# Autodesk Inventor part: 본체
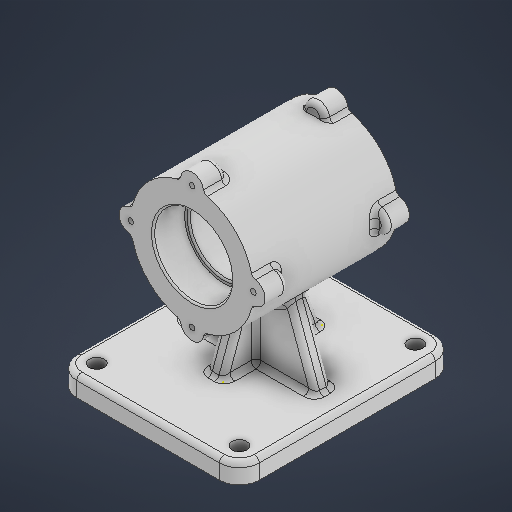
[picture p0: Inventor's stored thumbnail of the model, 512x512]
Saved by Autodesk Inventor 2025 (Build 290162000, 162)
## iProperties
Created: 2025-08
Part Number: 본체
Material: 일반
Document SubType Name: Modeling
Designer: infra012
Density: 1 g/cm^3
Appearance: 기본값
Author: infra012
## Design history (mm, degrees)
sketch "스케치1"
  geometry: 1 further point
sketch "스케치2"
  geometry: L1 (-55, -65)-(55, -65); L2 (55, -65)-(55, 65); L3 (55, 65)-(-55, 65); L4 (-55, 65)-(-55, -65); L5 (-55, -65)-(55, 65); L6 (55, -65)-(-55, 65); 1 further point
  constraints: 12 end point, 2 midpoint, 2 parallel, 1 horizontal, 1 perpendicular
  dimensions: "d0" = 110 distance of L3.end L2.end; "d1" = 130 distance of L2.end L1.end
extrude "돌출1" new body sketch "스케치2" distance "d2" = 12; taper "d3" = 0 deg
sketch "스케치3"
  geometry: 1 further point
sketch "스케치4"
  geometry: L1 (119, 38.5)-(82, 38.5); L2 (82, 38.5)-(82, -48.5); L3 (82, -48.5)-(119, -48.5); L4 (119, -48.5)-(119, 38.5); L5 (82, 38.5)-(105.5, 38.5); L6 (105.5, 38.5)-(105.5, 19.5); L7 (105.5, 19.5)-(82, 19.5); L8 (82, 19.5)-(82, 38.5); L9 (82, -48.5)-(105.5, -48.5); L10 (105.5, -48.5)-(105.5, -29.5); L11 (105.5, -29.5)-(82, -29.5); L12 (82, -29.5)-(82, -48.5); L13 (82, 19.5)-(103, 19.5); L14 (103, 19.5)-(103, -29.5); L15 (103, -29.5)-(82, -29.5); L16 (82, -29.5)-(82, 19.5); L17 (0, 65)-(12, 65) reference; L18 (0, 65)-(0, -65) reference; 6 further points
  constraints: 32 end point, 8 parallel, 4 horizontal, 4 perpendicular, 2 midpoint, 1 point on line
  dimensions: "d4" = 37 distance of L3.end L2.end; "d5" = 87 distance of L2.end L1.end; "d6" = 23.5 distance of L6.end L7.end; "d7" = 19 distance of L5.end L6.end; "d8" = 23.5 distance of L11.end L10.end; "d9" = 19 distance of L10.end L9.end; "d10" = 21 distance of L14.end L15.end; "d11" = 70 distance from line of point (82, -5) L17; "d12" = 82 distance from line of L18 point (82, -5)
revolve "회전1" sketch "스케치4" stored, may be unused: angle "d13" = 90 deg
sketch "스케치5"
  geometry: C1 r 7 at (0, 37); C2 r 7 at (-37, 0); C3 r 7 at (-37, 0); C4 r 7 at (0, -37); C5 r 7 at (37, 0); A1 r 37 centre (0, 0) between (0, 37) and (-37, 0) reference; 9 further points
  constraints: 5 centre point, 2 point on circle, 9 other
  dimensions: "d14" = 14 diameter of C1; "d15" = 14 diameter of C2; "d18" = 360 deg dimension on A1.centre C1.centre (derived)
extrude "돌출2" join sketch "스케치5" distance "d20" = 14; taper "d21" = 0 deg
sketch "스케치6"
  geometry: C1 r 7 at (0, 37); C2 r 7 at (-37, 0); C3 r 7 at (0, -37); C4 r 7 at (37, 0); 10 further points
  constraints: 4 centre point, 11 other
  dimensions: "d22" = 14 diameter of C1; "d25" = 360 deg dimension on point (0, 0) C1.centre (derived)
extrude "돌출3" join sketch "스케치6" distance "d27" = 14; taper "d28" = 0 deg
sketch "스케치7"
  geometry: 1 further point
node "스케치8"
sketch "스케치11"
  geometry: 1 further point
sketch "스케치12"
  geometry: 1 further point
sketch "스케치13"
  geometry: L1 (12, 25)-(58.061, 8.235); L2 (12, -35)-(55.537, -19.154); 3 further points
  constraints: 4 end point, 2 vertical alignment
  dimensions: "d35" = 60 distance of L2.start L1.start; "d36" = 40 distance of point (12, 65) L1.start
sketch "스케치14"
  geometry: 1 further point
sketch "스케치15"
  geometry: 1 further point
sketch "스케치16"
  geometry: 1 further point
sketch "스케치17"
  geometry: L1 (5, 35)-(-5, 35); L2 (-5, 35)-(-5, -25); L3 (-5, -25)-(5, -25); L4 (5, -25)-(5, 35); L5 (5, 35)-(-5, -25); L6 (-5, 35)-(5, -25); L7 (-55, -65)-(55, -65) reference; L8 (43, 10)-(-43, 10); L9 (-43, 10)-(-43, 0); L10 (-43, 0)-(43, 0); L11 (43, 0)-(43, 10); L12 (43, 10)-(-43, 0); L13 (-43, 10)-(43, 0); L14 (5, 0)-(-5, 0); L15 (-5, 0)-(-5, 10); L16 (-5, 10)-(5, 10); L17 (5, 10)-(5, 0); L18 (5, 0)-(-5, 10); L19 (-5, 0)-(5, 10); 6 further points
  constraints: 36 end point, 6 midpoint, 6 parallel, 3 horizontal, 3 perpendicular
  dimensions: "d39" = 10 distance of L3.end L2.end; "d40" = 60 distance of L2.end L1.end; "d41" = 70 distance from line of L7 point (0, 5); "d42" = 86 distance of L10.end L9.end; "d43" = 10 distance of L9.end L8.end; "d44" = 10 distance of L15.end L16.end; "d45" = 10 distance of L14.end L15.end
sketch "스케치18"
  geometry: 1 further point
sketch "스케치19"
  geometry: 1 further point
sketch "스케치20"
  geometry: 1 further point
extrude "돌출5" join sketch "스케치17" stored distance "d46" = 10; taper "d47" = 0 deg; dims "d4" = 37, "d5" = 87, "d6" = 23.5, "d7" = 19, "d8" = 23.5, "d9" = 19, "d10" = 21, "d11" = 70, "d12" = 82
sketch "스케치21"
  geometry: 1 further point
feature "리브1" dims "d48" = 1, "d49" = 10, "d50" = 0, "d51" = 0, "d52" = 1, "d53" = 1
sketch "스케치22"
  geometry: L1 (12, -35)-(50.309, -21.057); L2 (12, 65)-(12, -65) reference; 2 further points
  constraints: 2 end point, 1 vertical alignment
  dimensions: "d54" = 110 deg angle of L2 L1; "d55" = 60 distance of point (12, 25) L1.start
feature "리브2" sketch "스케치22" dims "d56" = 1, "d57" = 10, "d58" = 0, "d59" = 0, "d60" = 1, "d61" = 1
sketch "스케치23"
  geometry: L1 (5, 35)-(5, -25) reference; 2 further points
  constraints: 1 midpoint
sketch "스케치24"
  geometry: L1 (41, 12)-(20.479, 68.382); L2 (55, 12)-(-55, 12) reference; 1 further point
  constraints: 2 end point
  dimensions: "d62" = 14 distance of L2.start L1.start; "d63" = 60 distance of L1.start L1.end; "d64" = 110 deg angle of L2 L1; "d65" = 13.1557 distance from line of L2.start L1
feature "리브3" sketch "스케치24" dims "d66" = 1, "d67" = 10, "d68" = 0, "d69" = 0, "d70" = 1, "d71" = 1
sketch "스케치25"
  geometry: L1 (-41, 12)-(-22.486, 62.868); L2 (-55, 12)-(55, 12) reference; 1 further point
  constraints: 2 end point, 1 horizontal alignment
  dimensions: "d72" = 14 distance of L2.start L1.start; "d73" = 110 deg angle of L2 L1
feature "리브4" sketch "스케치25" dims "d74" = 1, "d75" = 10, "d76" = 0, "d77" = 0, "d78" = 1, "d79" = 1
sketch "스케치26"
  geometry: A1 r 7 centre (0, 0) between (6.969, -0.662) and (-6.969, -0.662) reference; A2 r 7 centre (-37, -37) between (-36.338, -30.031) and (-36.338, -43.969) reference; A3 r 7 centre (0, -74) between (-6.969, -73.338) and (6.969, -73.338) reference; A4 r 7 centre (37, -37) between (36.338, -43.969) and (36.338, -30.031) reference; 5 further points
  constraints: 4 coincident
hole "구멍1" sketch "스케치26" at (0, 0), (-37, -37), (0, -74), (37, -37) diameter "d80" = 3.242; stored, may be unused: countersink angle "d84" = 90 deg, drill point angle "d86" = 118 deg; dims "d81" = 8, "d82" = 4, "d83" = 2, "d85" = 10
sketch "스케치27"
  geometry: C1 r 1.621 at (0, 74) reference; C2 r 1.621 at (-37, 37) reference; C3 r 1.621 at (0, 0) reference; C4 r 1.621 at (37, 37) reference; 5 further points
  constraints: 4 coincident
hole "구멍2" sketch "스케치27" at (0, 74), (-37, 37), (0, 0), (37, 37) diameter "d87" = 3.242; stored, may be unused: countersink angle "d91" = 90 deg, drill point angle "d93" = 118 deg; dims "d88" = 8, "d89" = 4, "d90" = 2, "d92" = 10
sketch "스케치28"
  geometry: L1 (-43, -53)-(43, -53); L2 (43, -53)-(43, 53); L3 (43, 53)-(-43, 53); L4 (-43, 53)-(-43, -53); L5 (-43, -53)-(43, 53); L6 (43, -53)-(-43, 53); 5 further points
  constraints: 12 end point, 4 coincident, 2 midpoint, 2 parallel, 1 horizontal, 1 perpendicular
  dimensions: "d94" = 86 distance of L3.end L2.end; "d95" = 106 distance of L2.end L1.end
hole "구멍3" sketch "스케치28" at (43, 53), (-43, 53), (-43, -53), (43, -53) diameter "d96" = 9; stored, may be unused: countersink angle "d100" = 90 deg, drill point angle "d102" = 118 deg; dims "d97" = 8, "d98" = 4, "d99" = 2, "d101" = 10
fillet "모깎기1" dims "d103" = 12
fillet "모깎기2" dims "d104" = 3
fillet "모깎기3" dims "d105" = 3
fillet "모깎기4" dims "d106" = 3
fillet "모깎기5" dims "d107" = 1
node "솔리드1"
node "스케치 - 원형 패턴1" dims "d18" = 360 deg (derived)
node "스케치 - 원형 패턴2" dims "d25" = 360 deg (derived)
feature "A9D066F2-1C7D-4E18-AEED-F7BC21143FA4" dims "d96" = 9, "d97" = 8, "d98" = 4, "d99" = 2, "d100" = 90 deg, "d101" = 10, "d102" = 118 deg
